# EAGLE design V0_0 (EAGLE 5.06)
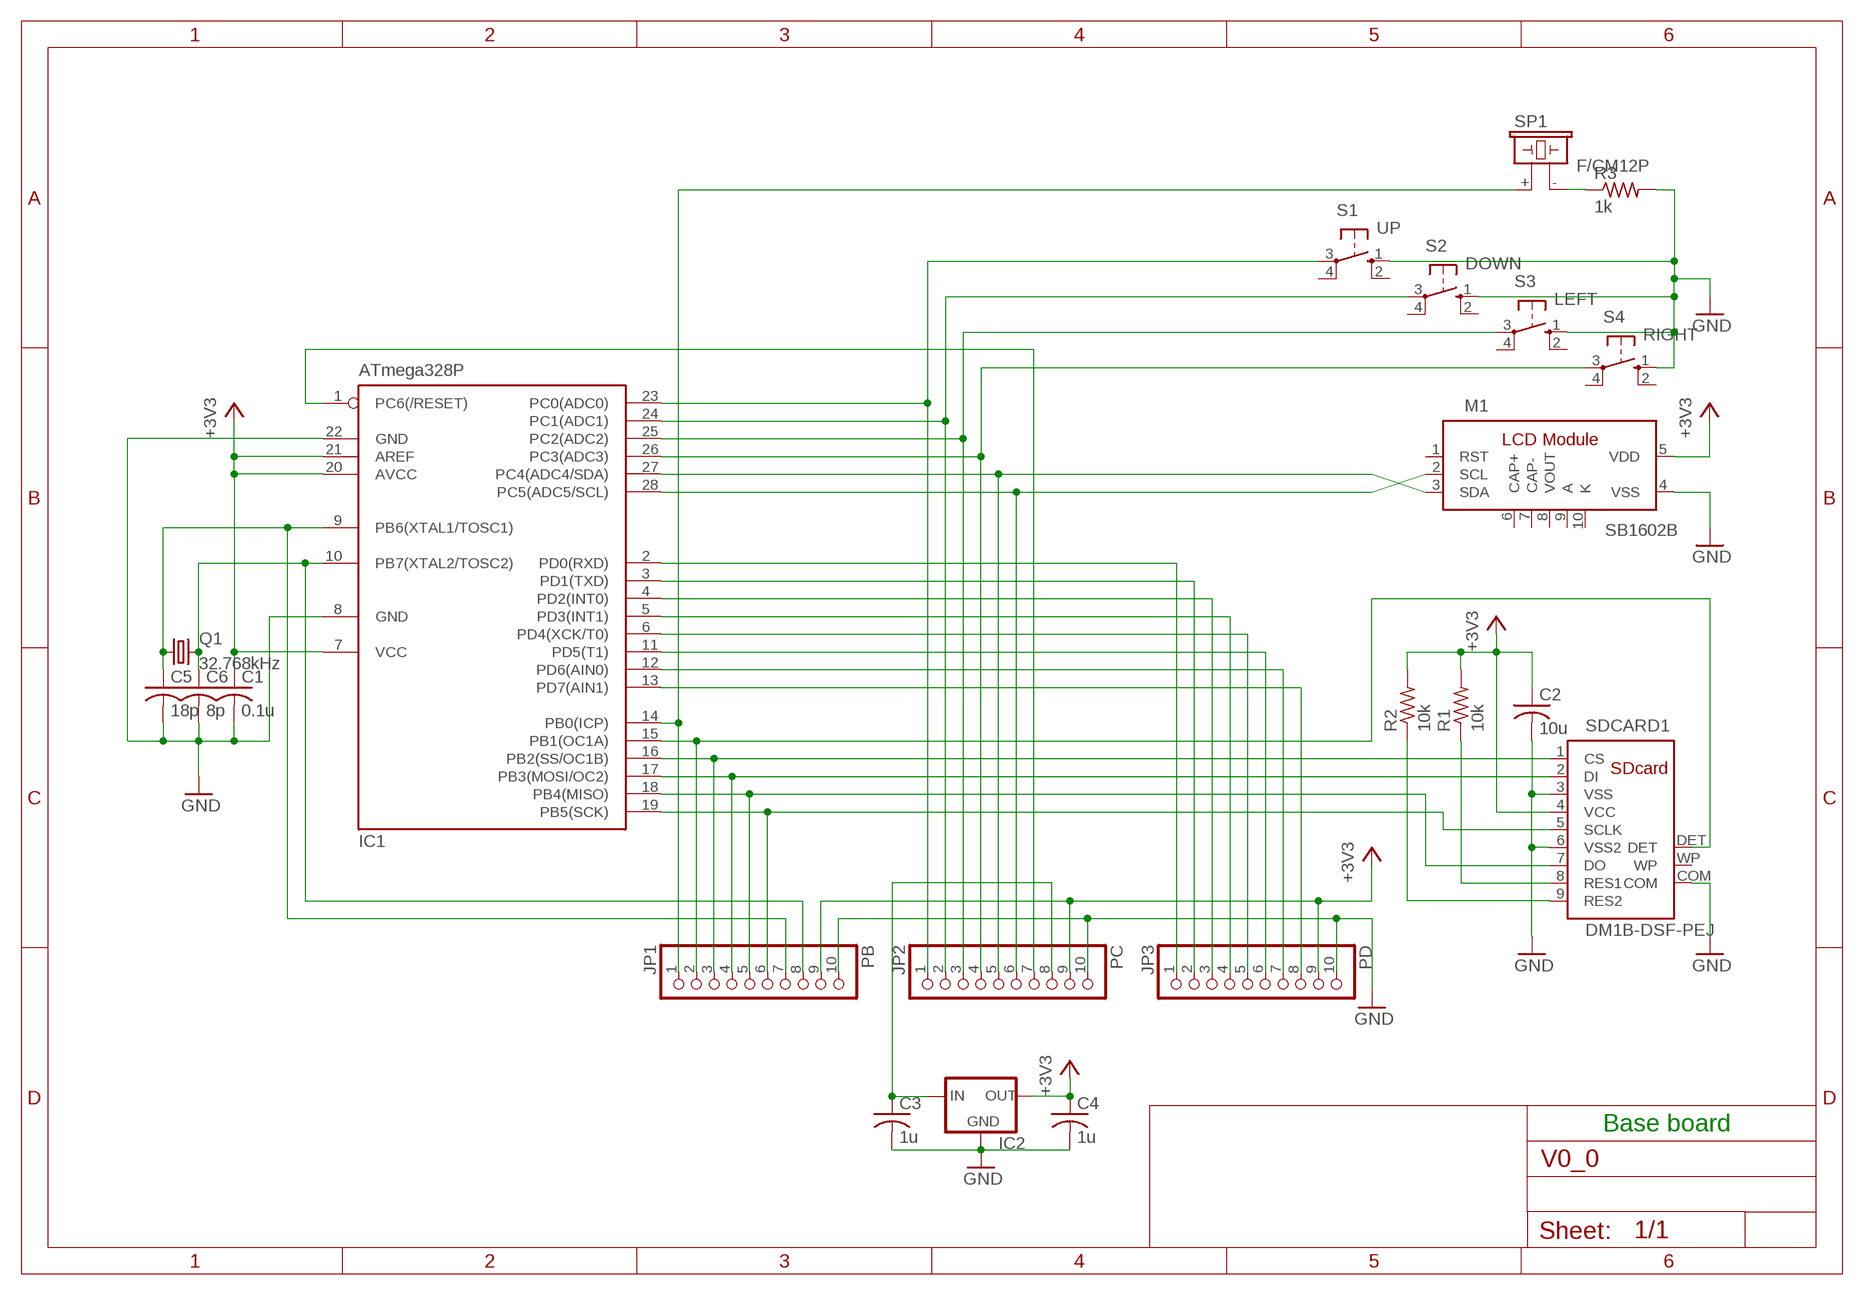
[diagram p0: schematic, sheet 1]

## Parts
C1  0.1u  C-US025-024X044  [C025-024X044]
C2  10u  C-US025-024X044  [C025-024X044]
C3  1u  C-US025-024X044  [C025-024X044]
C4  1u  C-US025-024X044  [C025-024X044]
C5  18p  C-US025-024X044  [C025-024X044]
C6  8p  C-US025-024X044  [C025-024X044]
IC1  ATmega328P  MEGA8-P  [DIL28-3]
IC2  XC63FPL  [TO92]
JP1  PB  PINHD-1X10  [1X10]
JP2  PC  PINHD-1X10  [1X10]
JP3  PD  PINHD-1X10  [1X10]
M1  SB1602B  [SB1602B]
Q1  32.768kHz  CRYSTALTC26H  [TC26H]
R1  10k  R-US_0204/5  [0204/5]
R2  10k  R-US_0204/5  [0204/5]
R3  1k  R-US_0204/5  [0204/5]
S1  UP  10-XX  [B3F-10XX]
S2  DOWN  10-XX  [B3F-10XX]
S3  LEFT  10-XX  [B3F-10XX]
S4  RIGHT  10-XX  [B3F-10XX]
SDCARD1  DM1B-DSF-PEJ  [DM1B]
SP1  F/CM12P  [F/CM12P]

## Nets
+3V3: C1.1 C2.1 C4.1 IC1.7(VCC) IC1.20(AVCC) IC1.21(AREF) IC2.3(OUT) JP1.9 JP2.9 JP3.9 M1.5(VDD) R1.2 R2.2 SDCARD1.4(VCC)
GND: C1.2 C2.2 C3.2 C4.2 C5.2 C6.2 IC1.8(GND) IC1.22(GND) IC2.2(GND) JP1.10 JP2.10 JP3.10 M1.4(VSS) R3.2 S1.1(S) S2.1(S) S3.1(S) S4.1(S) SDCARD1.3(VSS) SDCARD1.6(VSS2) SDCARD1.COM
N$1: IC1.16(PB2(SS/OC1B)) JP1.3 SDCARD1.1(CS)
N$2: IC1.17(PB3(MOSI/OC2)) JP1.4 SDCARD1.2(DI)
N$3: IC1.18(PB4(MISO)) JP1.5 SDCARD1.7(DO)
N$4: IC1.19(PB5(SCK)) JP1.6 SDCARD1.5(SCLK)
N$5: IC1.27(PC4(ADC4/SDA)) JP2.5 M1.3(SDA)
N$6: IC1.28(PC5(ADC5/SCL)) JP2.6 M1.2(SCL)
N$7: IC1.2(PD0(RXD)) JP3.1
N$8: IC1.3(PD1(TXD)) JP3.2
N$9: R1.1 SDCARD1.8(RES1)
N$10: R2.1 SDCARD1.9(RES2)
N$11: IC1.4(PD2(INT0)) JP3.3
N$12: IC1.5(PD3(INT1)) JP3.4
N$13: IC1.6(PD4(XCK/T0)) JP3.5
N$14: IC1.11(PD5(T1)) JP3.6
N$15: IC1.12(PD6(AIN0)) JP3.7
N$16: IC1.13(PD7(AIN1)) JP3.8
N$17: R3.1 SP1.-
N$18: IC1.23(PC0(ADC0)) JP2.1 S1.3(P)
N$19: IC1.24(PC1(ADC1)) JP2.2 S2.3(P)
N$20: IC1.25(PC2(ADC2)) JP2.3 S3.3(P)
N$21: IC1.26(PC3(ADC3)) JP2.4 S4.3(P)
N$22: IC1.14(PB0(ICP)) JP1.1 SP1.+
N$23: IC1.15(PB1(OC1A)) JP1.2 SDCARD1.DET
N$24: C5.1 IC1.9(PB6(XTAL1/TOSC1)) JP1.7 Q1.1
N$26: IC1.1(PC6(/RESET)) JP2.7
N$27: C3.1 IC2.1(IN) JP2.8
N$28: C6.1 IC1.10(PB7(XTAL2/TOSC2)) JP1.8 Q1.2
Unconnected: M1.1(RST) M1.6(CAP+) M1.7(CAP-) M1.8(VOUT) S1.2(S1) S1.4(P1) S2.2(S1) S2.4(P1) S3.2(S1) S3.4(P1) S4.2(S1) S4.4(P1) SDCARD1.WP

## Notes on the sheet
- Base board

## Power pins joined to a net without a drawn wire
A: M1.9(A)
K: M1.10(K)

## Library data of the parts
C1-C6 = rcl:C-US: CAPACITOR, American symbol
IC1 = atmel:MEGA8-P: MICROCONTROLLER 8 Kbytes FLASH, 1 kbytes SRAM, 512 bytes EEPROM, USART, 4-channel 10 bit ADC, 2-channel 8 bit ADC Pin compatible with Atmega48, ATMega88, ATMega168 Source: avr.lbr
IC2 = v-reg:XC63FP: Positiv Voltage Regulators www.torex.co.jp/english/product/pro02/pdf/0201_xc62fp.pdf
JP1-JP3 = pinhead:PINHD-1X10: PIN HEADER
M1 = TOG:SB1602B: Strawberry Linux Co.,Ltd. I2C LCD Module Controler: ST7032i
Q1 = crystal:CRYSTAL: CRYSTAL
R1-R3 = rcl:R-US_: RESISTOR, American symbol
S1-S4 = switch-omron:10-XX: OMRON SWITCH
SDCARD1 = TOG:DM1B-DSF-PEJ: SDcard connector reverse type HIROSE
SP1 = buzzer:F/CM12P: BUZZER

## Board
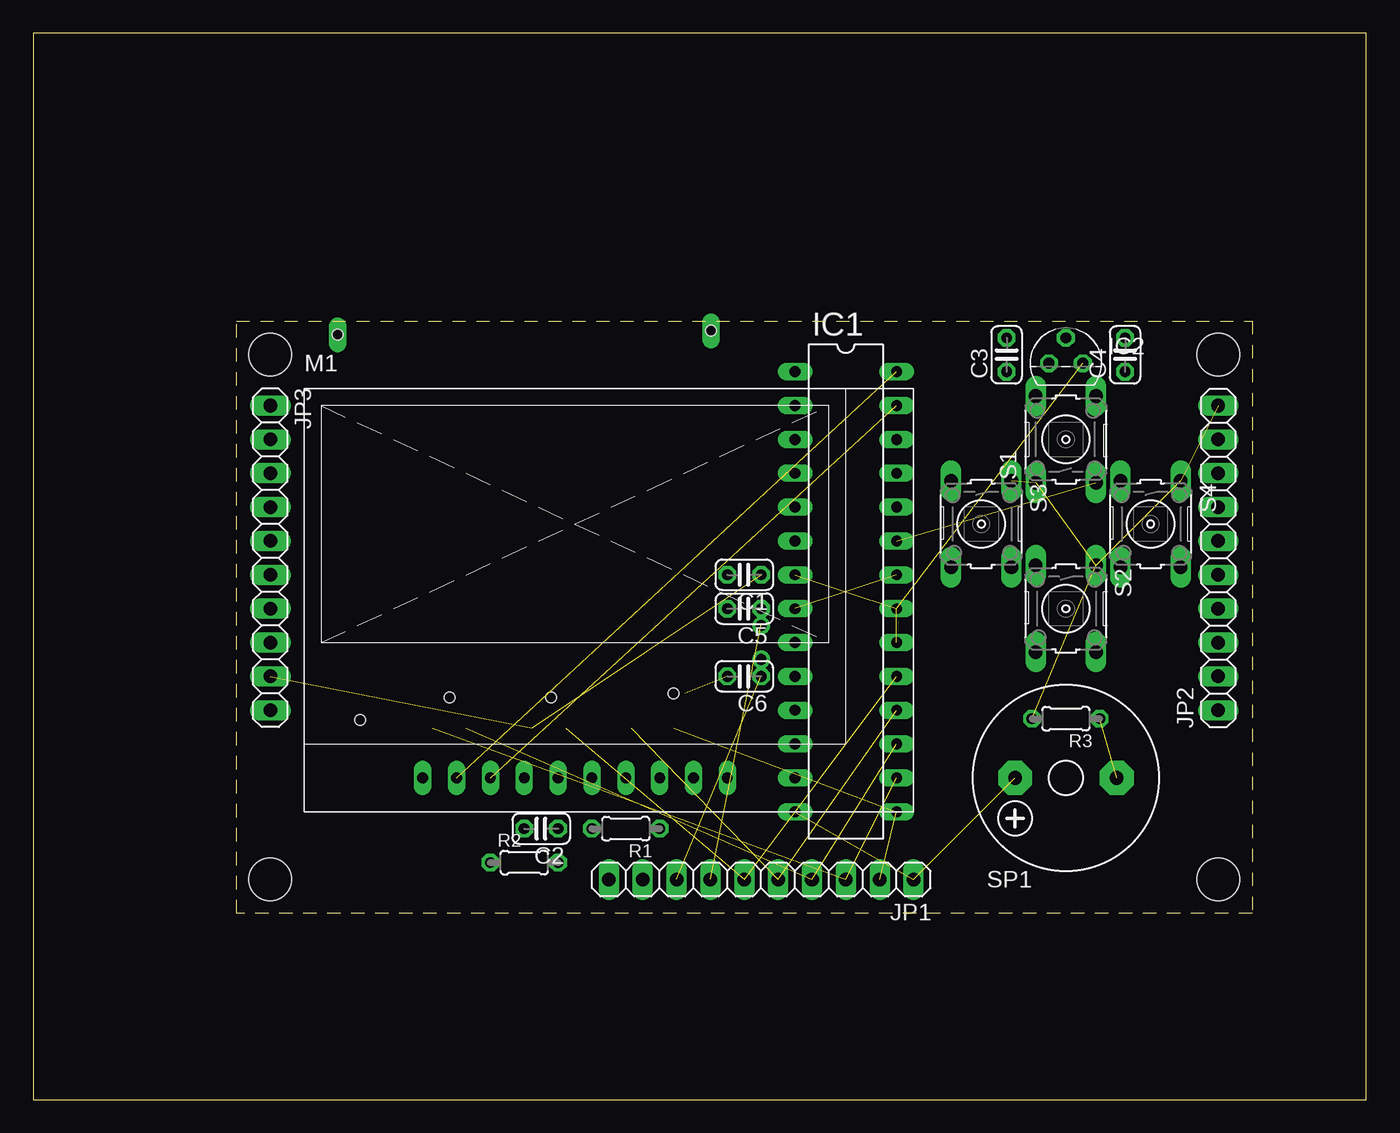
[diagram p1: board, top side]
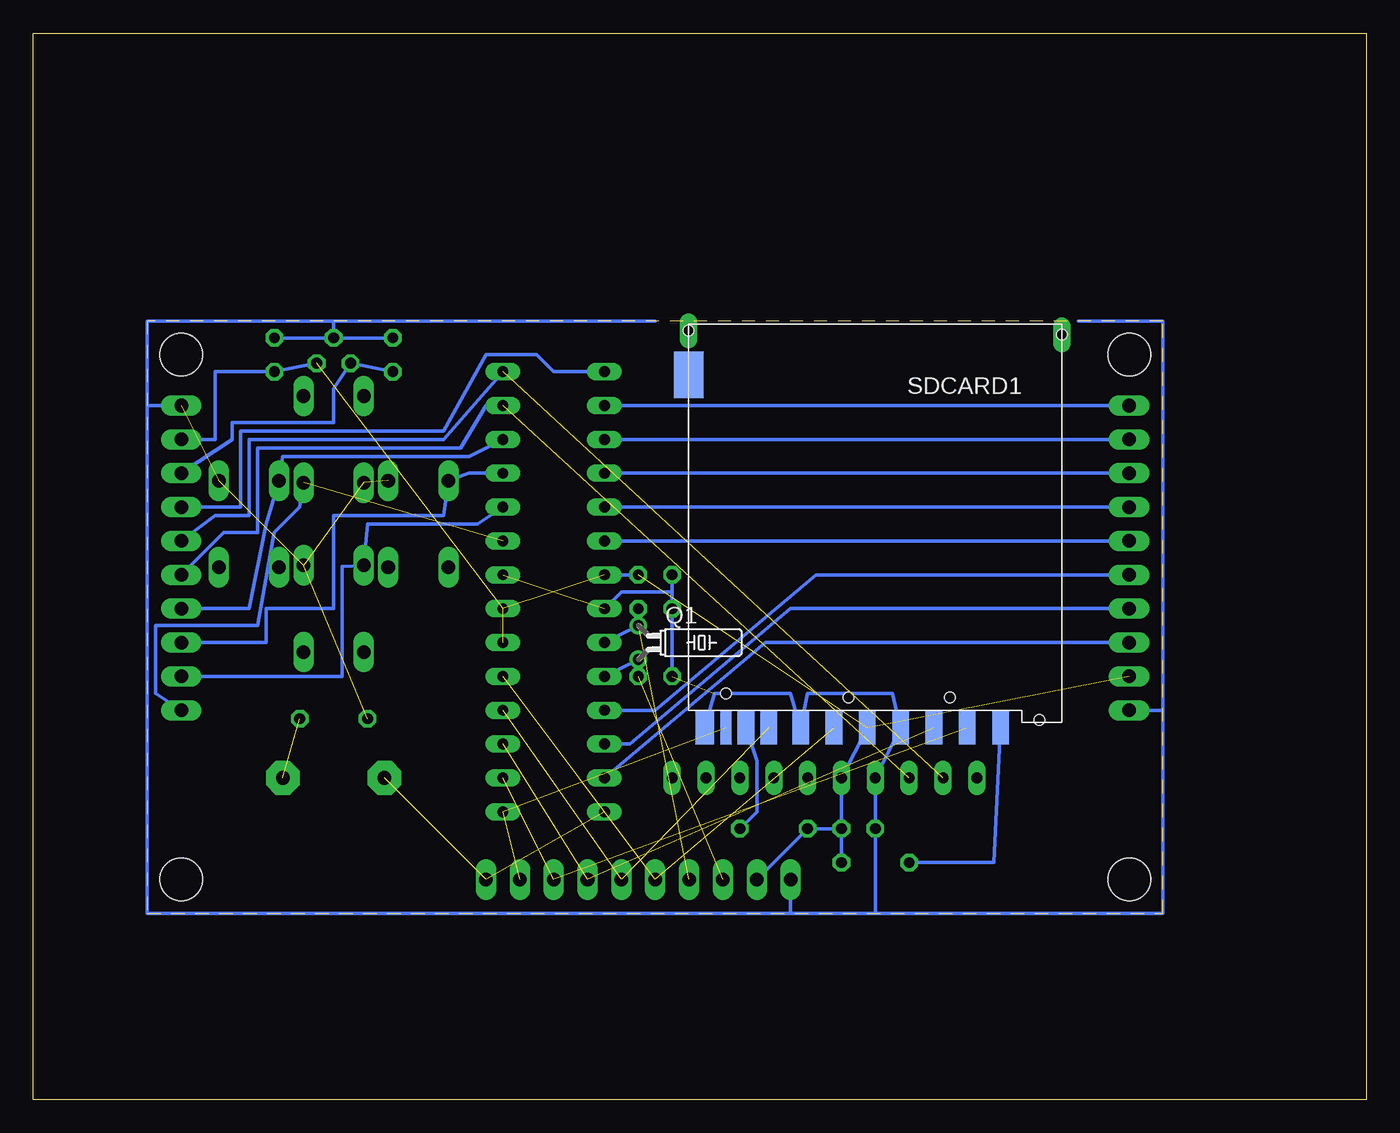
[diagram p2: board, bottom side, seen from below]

Size 100 x 80 mm. Coordinates in mm from the lower left corner, seen from the top.
Outline: 0,0 100,0 100,80 0,80 0,0
Outline: 15.24,58.42 91.44,58.42 91.44,13.97 15.24,13.97 15.24,58.42
Copper layers (1*16): Top 0.035mm / dielectric 1.5mm / Bottom 0.035mm
Design rules "default": minimum track width 10mil, minimum drill 24mil, track to track 8mil, track to pad 8mil, pad to pad 8mil, via to via 8mil, smd to smd 8mil, copper to edge 40mil, drill to drill 8mil, minimum pad ring 10mil, minimum via ring 8mil, stop-mask expansion 4mil, vias tented up to drill 0mil, thermal gap 10mil
Holes 3.2 mm at 17.78,55.88 88.9,55.88 88.9,16.51 17.78,16.51

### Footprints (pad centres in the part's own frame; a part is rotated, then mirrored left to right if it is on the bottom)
C025-024X044 = drill 0.813 octagon: 1 -1.27,0; 2 1.27,0
DIL28-3 = drill 0.813 long: 1 -16.51,-3.81; 2 -13.97,-3.81; 3 -11.43,-3.81; 4 -8.89,-3.81; 5 -6.35,-3.81; 6 -3.81,-3.81; 7 -1.27,-3.81; 8 1.27,-3.81; 9 3.81,-3.81; 10 6.35,-3.81; 11 8.89,-3.81; 12 11.43,-3.81; 13 13.97,-3.81; 14 16.51,-3.81; 15 16.51,3.81; 16 13.97,3.81; 17 11.43,3.81; 18 8.89,3.81; 19 6.35,3.81; 20 3.81,3.81; 21 1.27,3.81; 22 -1.27,3.81; 23 -3.81,3.81; 24 -6.35,3.81; 25 -8.89,3.81; 26 -11.43,3.81; 27 -13.97,3.81; 28 -16.51,3.81
TO92 = drill 0.813 octagon: 1 -1.27,0; 2 0,1.905; 3 1.27,0
1X10 = drill 1.016 long: 1 -11.43,0; 2 -8.89,0; 3 -6.35,0; 4 -3.81,0; 5 -1.27,0; 6 1.27,0; 7 3.81,0; 8 6.35,0; 9 8.89,0; 10 11.43,0
SB1602B = drill 0.8 long: 1 -13.97,-12.7; 2 -11.43,-12.7; 3 -8.89,-12.7; 4 -6.35,-12.7; 5 -3.81,-12.7; 6 -1.27,-12.7; 7 1.27,-12.7; 8 3.81,-12.7; 9 6.35,-12.7; 10 8.89,-12.7
TC26H = drill 0.813 round: 1 -1.27,0; 2 1.27,0
0204/5 = drill 0.813 octagon: 1 -2.54,0; 2 2.54,0
B3F-10XX = drill 1.016 long: 1 -3.251,2.261; 2 3.251,2.261; 3 -3.251,-2.261; 4 3.251,-2.261
DM1B = smd 1.25 x 2.5: 1 -6.9,15.3; 2 -4.4,15.3; 3 -1.9,15.3; 4 0.6,15.3; 5 3.1,15.3; 6 5.6,15.3; 7 8,15.3; 8 9.7,15.3; 9 -9.4,15.3 | smd 1.4 x 2.5: COM 12.8,15.3 | smd 0.8 x 2.5: DET 11.2,15.3 | drill 0.8 pad 1.2 long: P$17 14,-14.5 | drill 0.8 pad 1.27 long: P$18 -14,-14.2 | smd 2.2 x 3.5: WP 14,-11.2 | hole 0.8: -12.3,14.7; -5.6,13; 2,13; 11.2,12.7; -14,-14.2; 14,-14.5
F/CM12P = drill 1.016 pad 2.54 octagon: + 3.81,0; - -3.81,0

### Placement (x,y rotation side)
C1  53.34,39.37 180 top
C2  38.1,20.32 180 top
C3  73.03,55.88 90 top
C4  81.92,55.88 90 top
C5  53.34,36.83 180 top
C6  53.34,31.75 180 top
IC1  60.96,38.1 270 top
IC2  77.47,55.24 0 top
JP1  54.61,16.51 180 top
JP2  88.9,40.64 90 top
JP3  17.78,40.64 270 top
M1  43.18,36.83 0 top
Q1  54.61,34.29 270 bottom
R1  44.45,20.32 180 top
R2  36.83,17.78 0 top
R3  77.47,28.57 180 top
S1  77.47,49.53 90 top
S2  77.47,36.83 270 top
S3  71.12,43.18 270 top
S4  83.82,43.18 270 top
SDCARD1  36.83,43.18 180 bottom
SP1  77.47,24.13 180 top

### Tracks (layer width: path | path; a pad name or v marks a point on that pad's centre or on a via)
+3V3  (5 unrouted)
  Bottom 0.254: IC2.3 C4.1 86.36,54.61 86.36,49.53 JP2.9 | C1.1 IC1.7 | SDCARD1.4 M1.5 C2.1 | C2.1 R1.2 JP1.9 | R2.2 C2.1
GND  (7 unrouted)
  Bottom 0.254: 77.47,58.42 53.34,58.42 | 77.47,58.42 91.44,58.42 91.44,52.07 | 77.47,58.42 IC2.2 | IC2.2 C4.2 | IC2.2 C3.2 | 91.44,52.07 91.44,13.97 43.18,13.97 | 36.83,13.97 15.24,13.97 15.24,29.21 | 36.83,13.97 43.18,13.97 | 15.24,29.21 15.24,58.42 21.59,58.42 | 15.24,29.21 JP3.10 | 91.44,52.07 JP2.10 | 43.18,13.97 JP1.10 | IC1.8 55.88,38.1 52.07,38.1 | 52.07,38.1 C1.2 | 52.07,38.1 C5.2 C6.2 | SDCARD1.COM 48.9,30.48 43.18,30.48 SDCARD1.6 41.91,30.48 35.56,30.48 SDCARD1.3 M1.4 C2.2 36.83,13.97
N$1  (2 unrouted)
N$2  (2 unrouted)
N$3  (2 unrouted)
N$4  (2 unrouted)
N$5  (1 unrouted)
  Bottom 0.254: JP2.5 85.72,42.55 83.19,42.55 83.19,48.9 67.94,48.9 66.04,52.07 IC1.27
N$6  (1 unrouted)
  Bottom 0.254: JP2.6 86.36,43.81 83.82,43.81 83.82,49.53 69.22,49.53 IC1.28
N$7
  Bottom 0.254: IC1.2 JP3.1
N$8
  Bottom 0.254: IC1.3 JP3.2
N$9
  Bottom 0.254: R1.1 45.72,21.59 45.72,25.4 SDCARD1.8
N$10
  Bottom 0.254: R2.1 27.94,17.78 SDCARD1.9
N$11
  Bottom 0.254: IC1.4 JP3.3
N$12
  Bottom 0.254: IC1.5 JP3.4
N$13
  Bottom 0.254: IC1.6 JP3.5
N$14
  Bottom 0.254: IC1.11 53.34,29.21 41.27,39.37 JP3.6
N$15
  Bottom 0.254: IC1.12 55.24,26.67 43.18,36.83 JP3.7
N$16
  Bottom 0.254: IC1.13 45.09,34.29 JP3.8
N$17  (1 unrouted)
N$18  (1 unrouted)
  Bottom 0.254: JP2.1 90.81,30.48 90.81,35.56 83.19,35.56 81.92,42.55 80.01,44.45 S1.3
N$19
  Bottom 0.254: IC1.24 66.67,43.18 74.93,43.18 S2.3 76.83,40.01 76.83,31.75 JP2.2
N$20
  Bottom 0.254: IC1.25 67.31,46.99 S3.3 69.22,43.81 77.47,43.81 77.47,36.83 82.55,36.83 82.55,34.29 JP2.3
N$21
  Bottom 0.254: IC1.26 67.31,48.26 81.28,48.26 S4.3 82.55,43.18 83.82,36.83 JP2.4
N$22  (2 unrouted)
N$23  (2 unrouted)
N$24  (1 unrouted)
  Bottom 0.254: IC1.9 Q1.1 C5.1
N$26
  Bottom 0.254: JP2.7 84.45,44.45 84.45,50.16 69.22,50.16 66.04,55.88 62.23,55.88 60.96,54.61 IC1.1
N$27
  Bottom 0.254: C3.1 IC2.1 77.47,53.34 77.47,50.8 85.09,50.8 85.09,49.53 JP2.8
N$28  (1 unrouted)
  Bottom 0.254: IC1.10 Q1.2 C6.1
